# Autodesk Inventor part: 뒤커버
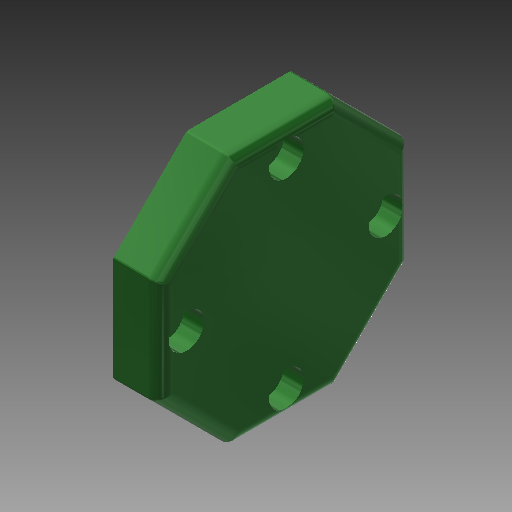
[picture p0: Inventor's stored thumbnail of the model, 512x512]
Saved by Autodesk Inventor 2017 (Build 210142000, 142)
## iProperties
Created: 2015-11
Part Number: 뒤커버
Material: 알루미늄 6061
Document SubType Name: Modeling
Designer: mduedu
Density: 1 g/cm^3
Appearance: 매끄러움 - 짙은 산림 녹색
Author: mduedu
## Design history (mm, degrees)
sketch "스케치5" dims "d66" = 58
  geometry: L1 (12.012, 29)-(29, 12.012); L2 (29, 12.012)-(29, -12.012); L3 (29, -12.012)-(12.012, -29); L4 (12.012, -29)-(-12.012, -29); L5 (-12.012, -29)-(-29, -12.012); L6 (-29, -12.012)-(-29, 12.012); L7 (-29, 12.012)-(-12.012, 29); L8 (-12.012, 29)-(12.012, 29); 4 further points
  constraints: 16 end point, 2 coincident, 2 vertical alignment, 1 midpoint, 19 other
extrude "돌출2" new body sketch "스케치5" distance "d67" = 11; taper "d68" = 0 deg
sketch "스케치6"
  geometry: C1 r 16 at (0, 0); 1 further point
  constraints: 1 centre point, 1 coincident
  dimensions: "d69" = 32 diameter of C1
extrude "돌출3" join sketch "스케치6" distance "d70" = 3; taper "d71" = 0 deg
hole "구멍5" diameter "d74" = 28; stored, may be unused: countersink angle "d78" = 90 deg, drill point angle "d80" = 0 deg; dims "d75" = 6, "d76" = 4, "d77" = 2, "d79" = 10, "d98" = 10, "d99" = 10
fillet "모깎기7" dims "d81" = 1
fillet "모깎기8" dims "d82" = 3
fillet "모깎기9" dims "d83" = 3
fillet "모깎기10" dims "d84" = 0.3
sketch "스케치7" dims "d85" = 46
  geometry: 3 further points
  constraints: 2 vertical alignment, 1 coincident, 2 other
hole "구멍6" sketch "스케치7" at (0, 23) diameter "d86" = 4.5; stored, may be unused: countersink angle "d90" = 90 deg, drill point angle "d92" = 0 deg; dims "d87" = 6, "d88" = 8, "d89" = 4.6, "d91" = 10
node "솔리드2"
pattern_circular "원형 패턴3" dims angle "d94" = 360 deg
